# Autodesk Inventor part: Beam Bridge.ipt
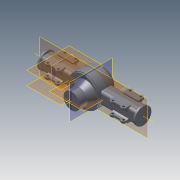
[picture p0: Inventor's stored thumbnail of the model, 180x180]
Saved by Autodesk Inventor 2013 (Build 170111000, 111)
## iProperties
Created: 2005-03
Part Number: Beam Bridge.ipt
Material: Steel, Mild
Document SubType Name: Modeling
Designer: salex
Manufacturer: Standard
Standards Organization: Custom
Density: 7.86 g/cm^3
Author: salex
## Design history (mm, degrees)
sketch "Эскиз1"
  geometry: L1 (0, 0)-(0, 183); L2 (0, 0)-(107.5, 0); L3 (107.5, 0)-(107.5, 100); L4 (107.5, 100)-(152.5, 183); L5 (152.5, 183)-(0, 183); L6 (295.69, 299)-(-200.814, 299); L7 (247.792, -104)-(-137.729, -104)
  constraints: 14 end point, 3 perpendicular, 2 parallel, 1 vertical, 1 other
  dimensions: "d1" = 215 diameter of L3 L1; "d3" = 305 diameter of L4.end L1; "d4" = 100 distance of L2.end L3.end; "d25" = 403 distance between parallel lines of L6 L7 (= d8); "d26" = 116 distance between parallel lines of L5 L6; "d27" = 104 distance between parallel lines of L7 L2 (= d9)
revolve "Вращение1" sketch "Эскиз1" stored, may be unused: angle "d6" = 90 deg
node "РабОсь1"
sketch "Эскиз2"
  geometry: L1 (0, 514.15)-(0, -151.55) reference; L2 (-152.5, 183)-(152.5, 183) reference; L3 (-30, 183)-(-30, 512.027); L4 (-30, 183)-(167.5, 183); L5 (167.5, 183)-(167.5, 199); L6 (167.5, 199)-(175, 199); L7 (175, 199)-(175, 389); L8 (-30, 509)-(99.414, 509); L9 (-240.7, 299)-(256.023, 299); L10 (-157.419, -104)-(169.635, -104); L11 (-107.5, 0)-(107.5, 0) reference; L12 (155, 389)-(175, 389); L13 (-30, 183)-(-30, 169.877); A1 r 202.604 centre (-30, 306.396) between (155, 389) and (-30, 509)
  constraints: 20 end point, 6 parallel, 3 perpendicular, 2 point on circle, 2 point on line, 1 centre point, 1 tangent
  dimensions: "d7" = 210 distance between parallel lines of L8 L9; "d8" = 403 distance between parallel lines of L9 L10; "d9" = 104 distance between parallel lines of L11 L10; "d12" = 395 diameter of L5 L3; "d13" = 30 distance between parallel lines of L1 L13; "d15" = 370 diameter of L12.start L3; "d24" = 410 diameter of L7 L3; "d28" = 100 distance between parallel lines of L6 L9; "d29" = 90 distance between parallel lines of L9 L12
revolve "Вращение2" sketch "Эскиз2" stored, may be unused: angle "d18" = 90 deg
node "РабОсь2"
node "РабПлоскость1"
sketch "Эскиз3"
  geometry: L1 (-85, -612.5)-(75, -612.5); L2 (75, -612.5)-(75, 672.5); L3 (75, 672.5)-(-85, 672.5); L4 (-85, 672.5)-(-85, -612.5); L5 (-367.7, 30)-(344.9, 30) reference; L6 (398, 362.151)-(398, -222.344); L7 (-5, 672.5)-(-5, -612.5); L8 (294, -77.5)-(294, 137.5) reference
  constraints: 12 end point, 2 midpoint, 2 parallel, 2 perpendicular, 1 horizontal
  dimensions: "d19" = 642.5 distance between parallel lines of L1 L5; "d20" = 642.5 distance between parallel lines of L3 L5 (= d19); "d21" = 160 distance of L2.end L3.end; "d22" = 403 distance between parallel lines of L7 L6 (= d8); "d23" = 104 distance between parallel lines of L6 L8 (= d9)
extrude "Выдавливание1" join sketch "Эскиз3" stored distance "d30" = 160 (= d21); taper "d31" = 0 deg
node "РабПлоскость3"
node "РабПлоскость4"
sketch "Эскиз5"
  geometry: L1 (-5, -622.453)-(-5, 638.532); L2 (294, -77.5)-(294, 137.5) reference
  constraints: 2 end point, 1 vertical
  dimensions: "d37" = 299 distance between parallel lines of L1 L2 (= d8 - d9)
  node "Спроецированная петля1"
node "РабОсь4"
sketch "Эскиз6"
  geometry: L1 (-130, -441.716)-(-130, -358.284); L2 (-120, -500)-(-50, -500); L3 (-50, -500)-(-50, -300); L4 (-50, -300)-(-120, -300); L5 (-5, -751.948)-(-5, 1060.986) reference; L6 (344.9, 30)-(-367.7, 30) reference; A1 r 30 centre (-120, -470) between (-130, -441.716) and (-120, -500); A2 r 30 centre (-120, -330) between (-120, -300) and (-130, -358.284)
  constraints: 8 end point, 4 point on circle, 3 perpendicular, 2 centre point, 2 tangent, 1 equal radius, 1 vertical
  dimensions: "d38" = 140 distance of A2.centre A1.centre; "d39" = 30 radius of A1; "d40" = 115 distance from line of A1.centre L5; "d41" = 70 distance from line of A1.centre L3; "d42" = 0 horizontal distance of A2.centre A1.centre; "d44" = 10 distance from line of A2.centre L1; "d45" = 500 distance from line of A1.centre L6
extrude "Выдавливание2" join sketch "Эскиз6" distance "d46" = 25; taper "d47" = 0 deg
node "РабПлоскость5"
sketch "Эскиз7"
  geometry: L1 (-85, -500)-(-85, -300) reference; L2 (-120, -500)-(-85, -500) reference; L3 (-130, -358.284)-(-130, -441.716) reference; L4 (-85, -300)-(-120, -300) reference; A1 r 30 centre (-120, -470) between (-130, -441.716) and (-120, -500) reference; A2 r 30 centre (-120, -330) between (-120, -300) and (-130, -358.284) reference
extrude "Выдавливание3" join sketch "Эскиз7" distance "d49" = 25; taper "d50" = 0 deg
node "РабПлоскость6"
mirror "ЗеркОтобр1"
sketch "Эскиз8"
  geometry: L1 (300, -110)-(300, -75) reference; L2 (500, -75)-(500, -110) reference; L3 (612.5, -75)-(500, -75) reference; L4 (500, 85)-(612.5, 85) reference; L5 (500, 85)-(500, 120) reference; L6 (300, 120)-(300, 85) reference; L7 (500, 97)-(300, 97); L8 (500, -87)-(300, -87); L9 (500, 97)-(500, -87); L10 (300, 91.158)-(300, -87)
  constraints: 8 end point, 5 point on line, 3 perpendicular, 1 parallel
  dimensions: "d52" = 12 distance between parallel lines of L4 L7; "d53" = 12 distance between parallel lines of L3 L8 (= d52)
extrude "Выдавливание4" join sketch "Эскиз8" distance "d54" = 14; taper "d55" = 0 deg
sketch "Эскиз9"
  geometry: L1 (-441.716, -120)-(-358.284, -120) reference; L2 (-300, -110)-(-300, -40) reference; L3 (-300, -40)-(-500, -40) reference; L4 (-500, -40)-(-500, -110) reference; C1 r 15 at (-470, 120); C2 r 15 at (-330, 120); C3 r 15 at (-470, -110); C4 r 15 at (-330, -110); A1 r 30 centre (-470, 120) between (-441.716, 130) and (-500, 120) reference; A2 r 30 centre (-330, 120) between (-300, 120) and (-358.284, 130) reference; A3 r 30 centre (-330, -110) between (-358.284, -120) and (-300, -110) reference; A4 r 30 centre (-470, -110) between (-500, -110) and (-441.716, -120) reference
  constraints: 4 centre point, 4 coincident, 3 equal radius
  dimensions: "d56" = 30 diameter of C1
extrude "Выдавливание5" cut sketch "Эскиз9" stored distance "d57" = 14; taper "d58" = 0 deg
mirror "ЗеркОтобр2"
node "РабПлоскость7"
mirror "ЗеркОтобр3"
sketch "Эскиз12"
  geometry: L1 (-5, 25)-(25, 25) reference; L2 (45, 15)-(45, 25) reference; L3 (45, 25)-(45, 15) reference; L4 (45, 175)-(45, 15) reference; L5 (45, 175)-(45, 150) reference; L6 (45, 150)-(45, 175) reference; L7 (45, 15)-(45, 175) reference; L8 (-5, 25)-(25, 25) reference; L9 (-5, 25)-(25, 25) reference; L10 (45, 25)-(10, 25) reference; L11 (10, 25)-(0, 25) reference; L12 (0, 25)-(10, 25) reference; L13 (10, 25)-(45, 25) reference; L14 (25, 150)-(-5, 150) reference; L15 (25, 150)-(-5, 150) reference; L16 (25, 150)-(-5, 150) reference; L17 (45, 150)-(10, 150) reference; L18 (10, 150)-(0, 150) reference; L19 (0, 150)-(10, 150) reference; L20 (10, 150)-(45, 150) reference; L21 (27.5, 150)-(45, 140); L22 (45, 140)-(45, 150); L23 (27.5, 150)-(45, 150); L24 (27.5, 25)-(35, 65); L25 (35, 65)-(45, 65); L26 (45, 65)-(45, 25); L27 (27.5, 25)-(45, 25)
  constraints: 14 end point, 4 collinear, 2 midpoint, 2 point on line, 1 perpendicular
  dimensions: "d70" = 40 distance between parallel lines of L13 L25; "d71" = 10 distance of L24.end L25.end; "d72" = 10 distance from line of L20 L21.end
extrude "Выдавливание8" join sketch "Эскиз12" stored distance "d73" = 200; taper "d74" = 0 deg
mirror "ЗеркОтобр4"
mirror "ЗеркОтобр5"
fillet "Сопряжение4" dims "d75" = 30
sketch "Эскиз13"
  geometry: C1 r 110 at (-80, 50); 1 further point
  constraints: 1 centre point, 1 coincident
  dimensions: "d76" = 220 diameter of C1
extrude "Выдавливание9" join sketch "Эскиз13" distance "d77" = 20; taper "d78" = 0 deg
mirror "ЗеркОтобр6"
body "Solid1"
node "Спроецированная петля2"
node "Спроецированная петля3"
node "Спроецированная петля8"
node "Спроецированная петля9"
node "Спроецированная петля10"
other parameters: "d32" = 95, "d33" = 90 deg, "d48" = -175, "d51" = 90 deg
